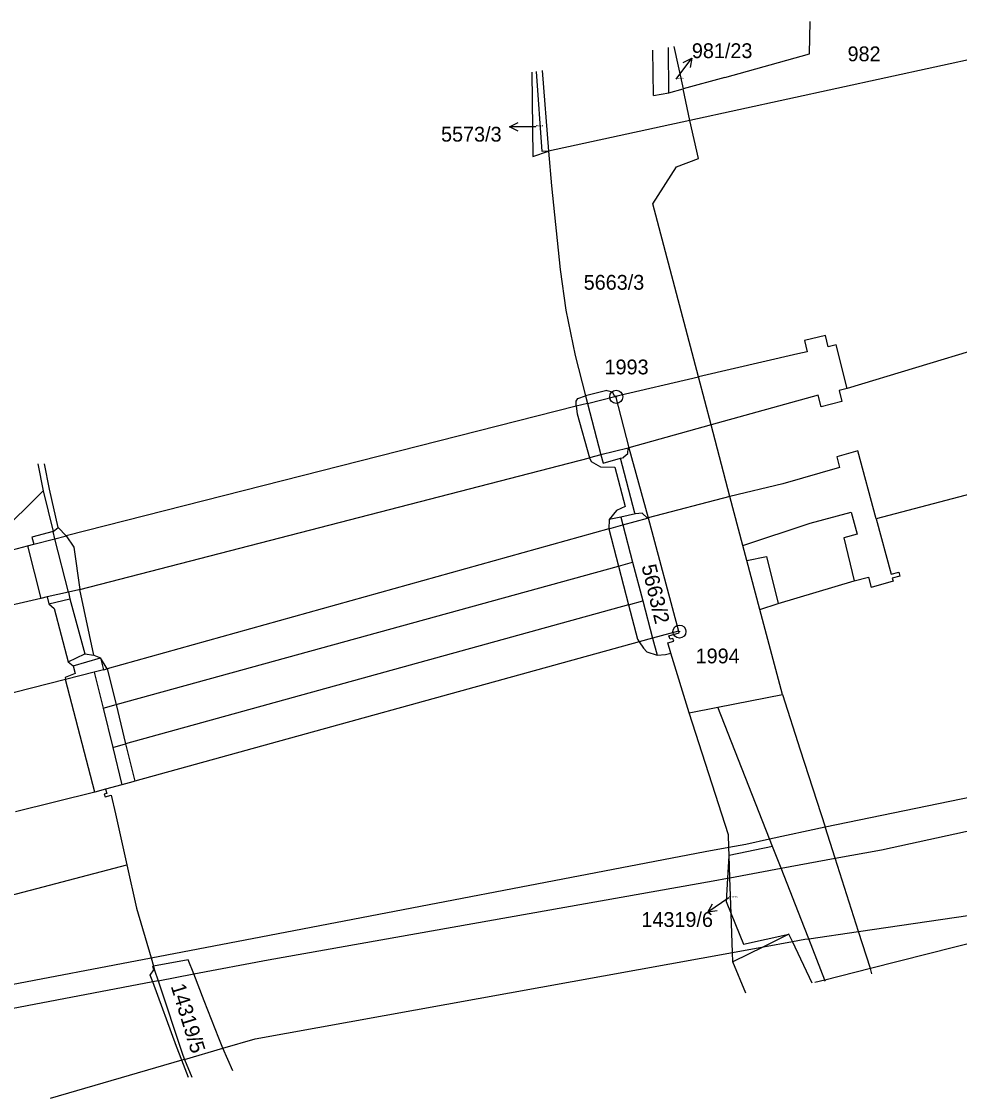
# Model space of a CAD drawing. Extents: x -825057 to -819383, y -1071633 to -1067888.
# Drawn here: x -822297.9 to -822190.2, y -1070466.7 to -1070343 of the extents above; entities that cross this region are included whole.
import ezdxf

# ---------------------------------------------------------------- set-up
doc = ezdxf.new("R2010")
doc.units = 0
for name, color, linetype in [('Vrstva 1', 7, 'Continuous'), ('Vrstva 16', 7, 'Continuous'), ('Vrstva 17', 7, 'Continuous'), ('Vrstva 18', 7, 'Continuous'), ('Vrstva 24', 7, 'Continuous'), ('Vrstva 4', 7, 'Continuous')]:
    doc.layers.add(name, color=color, linetype=linetype)

msp = doc.modelspace()

# ---------------------------------------------------------------- linework, layer by layer
at = {"layer": 'Vrstva 1'}
for p, q in [((-822207.39, -1070346.71), (-822207.31, -1070342.99)), ((-822065.38, -1070343.33), (-822203.06, -1070385.13)), ((-822223.55, -1070351.18), (-822223.57, -1070345.96)), ((-822222.96, -1070345.85), (-822221.89, -1070350.73)), ((-822182.14, -1070345.88), (-822221.11, -1070354.34)), ((-822217.12, -1070349.42), (-822207.39, -1070346.71)), ((-822239.25, -1070348.82), (-822239.15, -1070358.5)), ((-822238.07, -1070348.61), (-822237.35, -1070357.87)), ((-822217.12, -1070349.42), (-822221.89, -1070350.73)), ((-822223.55, -1070351.18), (-822221.89, -1070350.73)), ((-822221.11, -1070354.34), (-822221.89, -1070350.73)), ((-822221.11, -1070354.34), (-822237.35, -1070357.87)), ((-822220.13, -1070358.73), (-822221.11, -1070354.34)), ((-822239.15, -1070358.5), (-822237.35, -1070357.87)), ((-822237.35, -1070357.87), (-822237, -1070361.87)), ((-822222.67, -1070359.66), (-822220.13, -1070358.73)), ((-822225.38, -1070363.92), (-822222.67, -1070359.66)), ((-822237, -1070361.87), (-822236.02, -1070371.46)), ((-822060.87, -1070363.29), (-822199.72, -1070400.12)), ((-822220.14, -1070383.79), (-822225.38, -1070363.92)), ((-822236.02, -1070371.46), (-822235.38, -1070376.15)), ((-822235.38, -1070376.15), (-822234.28, -1070381.35)), ((-822205.53, -1070379.06), (-822207.95, -1070379.62)), ((-822207.95, -1070379.62), (-822207.65, -1070380.91)), ((-822205.23, -1070380.33), (-822205.53, -1070379.06)), ((-822207.65, -1070380.91), (-822208.73, -1070381.16)), ((-822204.32, -1070380.12), (-822205.23, -1070380.33)), ((-822203.06, -1070385.13), (-822204.32, -1070380.12)), ((-822234.28, -1070381.35), (-822233.12, -1070385.96)), ((-822208.73, -1070381.16), (-822220.14, -1070383.79)), ((-822218.69, -1070389.32), (-822220.14, -1070383.79)), ((-822230.65, -1070385.36), (-822233.12, -1070385.96)), ((-822233.12, -1070385.96), (-822232.89, -1070386.85)), ((-822230.63, -1070385.42), (-822230.65, -1070385.36)), ((-822230.02, -1070385.57), (-822230.63, -1070385.42)), ((-822229.74, -1070386.04), (-822230.02, -1070385.57)), ((-822229.67, -1070386.02), (-822229.74, -1070386.04)), ((-822229.67, -1070386.02), (-822228.14, -1070391.95)), ((-822232.89, -1070386.85), (-822234.17, -1070387.18)), ((-822234.17, -1070387.18), (-822234.07, -1070388.06)), ((-822234.07, -1070388.06), (-822232.64, -1070393.1)), ((-822216.52, -1070397.53), (-822218.69, -1070389.32)), ((-822228.14, -1070391.95), (-822225.92, -1070400)), ((-822232.64, -1070393.1), (-822232.44, -1070393.51)), ((-822295.99, -1070393.8), (-822295.37, -1070396.87)), ((-822232.44, -1070393.51), (-822231.37, -1070394.14)), ((-822231.37, -1070394.14), (-822229.75, -1070394.15)), ((-822229.75, -1070394.15), (-822228.54, -1070398.67)), ((-822295.37, -1070396.87), (-822300.62, -1070402.06)), ((-822295.37, -1070396.87), (-822294.23, -1070401.54)), ((-822215.04, -1070403.17), (-822216.52, -1070397.53)), ((-822229.55, -1070399.16), (-822230.37, -1070400.19)), ((-822228.54, -1070398.67), (-822229.55, -1070399.16)), ((-822230.37, -1070400.19), (-822230.43, -1070401.26)), ((-822225.92, -1070400), (-822222.41, -1070413)), ((-822199.72, -1070400.12), (-822198, -1070406.45)), ((-822294.23, -1070401.54), (-822293.68, -1070401.09)), ((-822293.68, -1070401.09), (-822292.73, -1070402.05)), ((-822292.73, -1070402.05), (-822291.88, -1070403.36)), ((-822230.43, -1070401.26), (-822229.32, -1070405.52)), ((-822291.88, -1070403.36), (-822291.16, -1070408.23)), ((-822214.58, -1070404.89), (-822215.04, -1070403.17)), ((-822229.32, -1070405.52), (-822228.15, -1070409.98)), ((-822213.1, -1070410.53), (-822214.58, -1070404.89)), ((-822202.24, -1070407.22), (-822200.61, -1070406.79)), ((-822200.61, -1070406.79), (-822200.29, -1070407.97)), ((-822198, -1070406.45), (-822197.12, -1070406.21)), ((-822196.99, -1070406.69), (-822197.87, -1070406.93)), ((-822197.87, -1070406.93), (-822197.78, -1070407.26)), ((-822197.12, -1070406.21), (-822196.99, -1070406.69)), ((-822291.3, -1070408.27), (-822292.47, -1070408.53)), ((-822291.16, -1070408.23), (-822291.3, -1070408.27)), ((-822210.97, -1070409.81), (-822202.24, -1070407.22)), ((-822197.78, -1070407.26), (-822200.29, -1070407.97)), ((-822295.67, -1070409.24), (-822304.46, -1070411.3)), ((-822294.91, -1070409.07), (-822295.67, -1070409.24)), ((-822292.47, -1070408.53), (-822294.91, -1070409.07)), ((-822292.47, -1070408.53), (-822292.33, -1070409.3)), ((-822292.33, -1070409.3), (-822290.61, -1070415.61)), ((-822228.15, -1070409.98), (-822227.14, -1070413.91)), ((-822213.1, -1070410.53), (-822210.97, -1070409.81)), ((-822210.49, -1070420.26), (-822213.1, -1070410.53)), ((-822222.41, -1070413), (-822225.4, -1070413.79)), ((-822223.54, -1070413.52), (-822222.36, -1070413.18)), ((-822222.36, -1070413.18), (-822222.41, -1070413)), ((-822226.94, -1070414.22), (-822284.87, -1070430.22)), ((-822227.14, -1070413.91), (-822226.94, -1070414.22)), ((-822225.4, -1070413.79), (-822226.94, -1070414.22)), ((-822223.65, -1070414.34), (-822222.96, -1070414.15)), ((-822223.32, -1070415.54), (-822223.65, -1070414.34)), ((-822223.4, -1070413.91), (-822223.54, -1070413.52)), ((-822223.09, -1070413.84), (-822223.4, -1070413.91)), ((-822222.96, -1070414.15), (-822223.09, -1070413.84)), ((-822290.61, -1070415.61), (-822289.56, -1070415.76)), ((-822289.56, -1070415.76), (-822288.8, -1070416.05)), ((-822221.19, -1070422.39), (-822223.32, -1070415.54)), ((-822288.8, -1070416.05), (-822288.44, -1070417.43)), ((-822289.52, -1070417.71), (-822292.81, -1070418.55)), ((-822288.44, -1070417.43), (-822289.52, -1070417.71)), ((-822288.44, -1070417.43), (-822288.03, -1070417.32)), ((-822288.03, -1070417.32), (-822287.02, -1070421.43)), ((-822292.81, -1070418.55), (-822302.04, -1070420.92)), ((-822217.92, -1070421.74), (-822210.49, -1070420.26)), ((-822210.49, -1070420.26), (-822208.44, -1070426.65)), ((-822287.02, -1070421.43), (-822285.92, -1070425.95)), ((-822221.19, -1070422.39), (-822217.92, -1070421.74)), ((-822216.69, -1070436.38), (-822221.19, -1070422.39)), ((-822285.92, -1070425.95), (-822284.87, -1070430.22)), ((-822208.44, -1070426.65), (-822205.6, -1070435.48)), ((-822285.1, -1070430.29), (-822286.36, -1070430.64)), ((-822284.87, -1070430.22), (-822285.1, -1070430.29)), ((-822205.6, -1070435.48), (-822181.45, -1070430.48)), ((-822289.45, -1070431.49), (-822298.56, -1070433.75)), ((-822288.24, -1070431.16), (-822289.45, -1070431.49)), ((-822288.08, -1070431.63), (-822288.37, -1070431.72)), ((-822288.37, -1070431.72), (-822288.27, -1070432.02)), ((-822286.36, -1070430.64), (-822288.24, -1070431.16)), ((-822288.24, -1070431.16), (-822288.08, -1070431.63)), ((-822288.27, -1070432.02), (-822287.56, -1070431.85)), ((-822287.56, -1070431.85), (-822287.07, -1070433.97)), ((-822287.07, -1070433.97), (-822285.76, -1070439.85)), ((-822216.64, -1070437.82), (-822216.69, -1070436.38)), ((-822216.61, -1070438.78), (-822216.64, -1070437.82)), ((-822216.64, -1070438.79), (-822216.79, -1070441.37)), ((-822216.61, -1070438.78), (-822216.64, -1070438.79)), ((-822216.52, -1070441.32), (-822216.61, -1070438.78)), ((-822305.9, -1070445.1), (-822285.76, -1070439.85)), ((-822285.76, -1070439.85), (-822284.66, -1070444.82)), ((-822216.79, -1070441.37), (-822216.94, -1070444.04)), ((-822216.37, -1070445.45), (-822216.52, -1070441.32)), ((-822216.94, -1070444.04), (-822216.37, -1070445.45)), ((-822284.66, -1070444.82), (-822283, -1070450.52)), ((-822216.22, -1070449.9), (-822216.37, -1070445.45)), ((-822209.74, -1070447.82), (-822212.68, -1070449.26)), ((-822209.34, -1070448.65), (-822209.74, -1070447.82)), ((-822207.07, -1070453.41), (-822209.34, -1070448.65)), ((-822216.18, -1070450.97), (-822216.22, -1070449.9)), ((-822212.68, -1070449.26), (-822216.18, -1070450.97)), ((-822283, -1070450.52), (-822282.72, -1070451.47)), ((-822278.72, -1070450.74), (-822282.72, -1070451.47)), ((-822282.72, -1070451.47), (-822282.59, -1070451.93)), ((-822278.09, -1070452.37), (-822278.72, -1070450.74)), ((-822214.71, -1070454.57), (-822216.18, -1070450.97)), ((-822282.59, -1070451.93), (-822282.19, -1070453.15)), ((-822276.91, -1070455.44), (-822278.09, -1070452.37)), ((-822282.19, -1070453.15), (-822279.36, -1070461.71)), ((-822275.23, -1070459.76), (-822276.91, -1070455.44)), ((-822274.74, -1070460.9), (-822275.23, -1070459.76)), ((-822273.62, -1070463.5), (-822274.74, -1070460.9)), ((-822279.36, -1070461.71), (-822279.16, -1070462.19)), ((-822279.16, -1070462.19), (-822278.33, -1070464.21))]:
    msp.add_line(p, q, dxfattribs=at)
at = {"layer": 'Vrstva 16'}
for p, q in [((-822222.68, -1070349.59), (-822220.886, -1070347.185)), ((-822238.82, -1070355.08), (-822241.82, -1070355.08)), ((-822238.81, -1070355.08), (-822238.82, -1070355.08)), ((-822216.66, -1070443.62), (-822219.061, -1070445.264))]:
    msp.add_line(p, q, dxfattribs=at)
for points in [[(-822221.885, -1070347.688), (-822220.886, -1070347.185), (-822221.083, -1070348.286)], [(-822240.82, -1070355.58), (-822241.82, -1070355.08), (-822240.82, -1070354.58)], [(-822217.987, -1070445.116), (-822219.061, -1070445.264), (-822218.535, -1070444.316)]]:
    msp.add_lwpolyline(points, dxfattribs=at)
at = {"layer": 'Vrstva 24'}
for centre, radius in [((-822229.58, -1070386.09), 0.75), ((-822229.58, -1070386.09), 0.0327), ((-822222.32, -1070413.05), 0.75), ((-822222.32, -1070413.05), 0.0327)]:
    msp.add_circle(centre, radius, dxfattribs=at)
at = {"layer": 'Vrstva 4'}
for p, q in [((-822225.28, -1070351.47), (-822225.38, -1070346.29)), ((-822238.1, -1070357.92), (-822238.73, -1070348.73)), ((-822225.28, -1070351.47), (-822223.55, -1070351.18)), ((-822237.35, -1070357.87), (-822238.1, -1070357.92)), ((-822229.67, -1070386.02), (-822220.14, -1070383.79)), ((-822233.97, -1070386.29), (-822233.12, -1070385.96)), ((-822232.89, -1070386.85), (-822229.74, -1070386.04)), ((-822206.4, -1070385.91), (-822218.69, -1070389.32)), ((-822206.03, -1070387.23), (-822206.4, -1070385.91)), ((-822203.06, -1070385.13), (-822203.99, -1070385.35)), ((-822203.99, -1070385.35), (-822203.67, -1070386.64)), ((-822234.17, -1070387.18), (-822292.73, -1070402.05)), ((-822234.17, -1070386.57), (-822233.97, -1070386.29)), ((-822234.17, -1070387.18), (-822234.17, -1070386.57)), ((-822232.89, -1070386.85), (-822231.33, -1070392.77)), ((-822203.67, -1070386.64), (-822206.03, -1070387.23)), ((-822218.69, -1070389.32), (-822228.14, -1070391.95)), ((-822228.2, -1070391.97), (-822231.33, -1070392.77)), ((-822228.25, -1070392.59), (-822228.2, -1070391.97)), ((-822228.14, -1070391.95), (-822228.2, -1070391.97)), ((-822291.16, -1070408.23), (-822232.64, -1070393.1)), ((-822231.33, -1070392.77), (-822232.64, -1070393.1)), ((-822231.33, -1070392.77), (-822231.08, -1070393.69)), ((-822231.08, -1070393.69), (-822229.07, -1070393.15)), ((-822229.07, -1070393.15), (-822228.69, -1070393.05)), ((-822227.43, -1070399.46), (-822229.07, -1070393.15)), ((-822228.71, -1070392.97), (-822228.25, -1070392.59)), ((-822228.69, -1070393.05), (-822228.71, -1070392.97)), ((-822201.84, -1070392.29), (-822204.24, -1070392.98)), ((-822204.24, -1070392.98), (-822203.92, -1070394.21)), ((-822199.72, -1070400.12), (-822201.84, -1070392.29)), ((-822294.64, -1070396.69), (-822295.23, -1070393.78)), ((-822203.92, -1070394.21), (-822210.43, -1070396.09)), ((-822293.68, -1070401.09), (-822294.64, -1070396.69)), ((-822210.43, -1070396.09), (-822216.52, -1070397.53)), ((-822216.52, -1070397.53), (-822225.92, -1070400)), ((-822227.35, -1070399.54), (-822229.05, -1070399.91)), ((-822227.35, -1070399.54), (-822227.43, -1070399.46)), ((-822226.58, -1070399.44), (-822227.35, -1070399.54)), ((-822226, -1070400.02), (-822226.58, -1070399.44)), ((-822207.31, -1070400.61), (-822202.58, -1070399.34)), ((-822202.58, -1070399.34), (-822201.89, -1070401.87)), ((-822230.43, -1070401.26), (-822228.81, -1070400.81)), ((-822229.05, -1070399.91), (-822230.37, -1070400.19)), ((-822229.05, -1070399.91), (-822228.81, -1070400.81)), ((-822228.81, -1070400.81), (-822226, -1070400.02)), ((-822228.81, -1070400.81), (-822227.69, -1070405.07)), ((-822225.92, -1070400), (-822226, -1070400.02)), ((-822215.04, -1070403.17), (-822207.31, -1070400.61)), ((-822294.23, -1070401.54), (-822296.67, -1070402.19)), ((-822294.03, -1070402.39), (-822294.23, -1070401.54)), ((-822294.03, -1070402.39), (-822292.87, -1070402.08)), ((-822292.87, -1070402.08), (-822292.73, -1070402.05)), ((-822230.43, -1070401.26), (-822288.03, -1070417.32)), ((-822201.89, -1070401.87), (-822203.42, -1070402.29)), ((-822306.02, -1070405.56), (-822297.18, -1070403.22)), ((-822297.18, -1070403.22), (-822296.44, -1070403.03)), ((-822297.18, -1070403.22), (-822295.67, -1070409.24)), ((-822296.67, -1070402.19), (-822296.44, -1070403.03)), ((-822296.44, -1070403.03), (-822294.03, -1070402.39)), ((-822292.47, -1070408.53), (-822294.03, -1070402.39)), ((-822203.42, -1070402.29), (-822202.24, -1070407.22)), ((-822214.58, -1070404.89), (-822212.31, -1070404.42)), ((-822212.31, -1070404.42), (-822210.97, -1070409.81)), ((-822287.02, -1070421.43), (-822229.32, -1070405.52)), ((-822229.32, -1070405.52), (-822227.69, -1070405.07)), ((-822227.69, -1070405.07), (-822226.52, -1070409.53)), ((-822289.56, -1070415.76), (-822291.16, -1070408.23)), ((-822294.91, -1070409.07), (-822294.73, -1070409.87)), ((-822294.73, -1070409.87), (-822292.33, -1070409.3)), ((-822228.15, -1070409.98), (-822226.52, -1070409.53)), ((-822226.52, -1070409.53), (-822225.4, -1070413.79)), ((-822294.73, -1070409.87), (-822294.12, -1070410.41)), ((-822294.12, -1070410.41), (-822292.53, -1070416.52)), ((-822228.15, -1070409.98), (-822285.92, -1070425.95)), ((-822226.94, -1070414.22), (-822226.46, -1070414.97)), ((-822225.4, -1070413.79), (-822224.88, -1070415.77)), ((-822292.53, -1070416.52), (-822290.61, -1070415.61)), ((-822226.46, -1070414.97), (-822226.08, -1070415.38)), ((-822226.08, -1070415.38), (-822224.88, -1070415.77)), ((-822224.88, -1070415.77), (-822223.92, -1070415.68)), ((-822223.92, -1070415.68), (-822223.32, -1070415.54)), ((-822292.53, -1070416.52), (-822291.96, -1070416.99)), ((-822291.96, -1070416.99), (-822288.8, -1070416.05)), ((-822291.96, -1070416.99), (-822291.7, -1070417.87)), ((-822288.03, -1070417.32), (-822288.8, -1070416.05)), ((-822291.7, -1070417.87), (-822292.87, -1070418.33)), ((-822289.52, -1070417.71), (-822288.51, -1070421.84)), ((-822292.87, -1070418.33), (-822292.81, -1070418.55)), ((-822289.45, -1070431.49), (-822292.81, -1070418.55)), ((-822288.51, -1070421.84), (-822287.02, -1070421.43)), ((-822288.51, -1070421.84), (-822287.4, -1070426.36)), ((-822211.96, -1070436.87), (-822217.92, -1070421.74)), ((-822287.4, -1070426.36), (-822285.92, -1070425.95)), ((-822287.4, -1070426.36), (-822286.36, -1070430.64)), ((-822199.12, -1070438.1), (-822181.48, -1070434.25)), ((-822211.96, -1070436.87), (-822205.6, -1070435.48)), ((-822204.44, -1070439.08), (-822205.6, -1070435.48)), ((-822219.37, -1070438.32), (-822216.64, -1070437.82)), ((-822216.64, -1070437.82), (-822214.69, -1070437.47)), ((-822211.62, -1070437.75), (-822216.61, -1070438.78)), ((-822214.69, -1070437.47), (-822211.96, -1070436.87)), ((-822211.62, -1070437.75), (-822211.96, -1070436.87)), ((-822210.64, -1070440.23), (-822211.62, -1070437.75)), ((-822270.38, -1070448.1), (-822219.37, -1070438.32)), ((-822210.64, -1070440.23), (-822204.44, -1070439.08)), ((-822204.44, -1070439.08), (-822199.12, -1070438.1)), ((-822201.74, -1070447.49), (-822204.44, -1070439.08)), ((-822216.52, -1070441.32), (-822210.64, -1070440.23)), ((-822207.95, -1070447.07), (-822210.64, -1070440.23)), ((-822269.55, -1070450.74), (-822218.44, -1070441.68)), ((-822218.44, -1070441.68), (-822216.79, -1070441.37)), ((-822216.79, -1070441.37), (-822216.52, -1070441.32)), ((-822201.74, -1070447.49), (-822165.38, -1070442.19)), ((-822165.23, -1070442.81), (-822200.38, -1070451.74)), ((-822216.37, -1070445.45), (-822214.97, -1070448.94)), ((-822214.97, -1070448.94), (-822209.74, -1070447.82)), ((-822207.46, -1070448.32), (-822207.95, -1070447.07)), ((-822207.46, -1070448.32), (-822201.74, -1070447.49)), ((-822200.38, -1070451.74), (-822201.74, -1070447.49)), ((-822283, -1070450.52), (-822270.38, -1070448.1)), ((-822212.68, -1070449.26), (-822209.34, -1070448.65)), ((-822209.34, -1070448.65), (-822207.91, -1070448.39)), ((-822207.91, -1070448.39), (-822207.46, -1070448.32)), ((-822205.61, -1070453.07), (-822207.46, -1070448.32)), ((-822271.05, -1070459.83), (-822216.22, -1070449.9)), ((-822216.22, -1070449.9), (-822212.68, -1070449.26)), ((-822301.4, -1070454.05), (-822283, -1070450.52)), ((-822282.8, -1070451.48), (-822282.72, -1070451.47)), ((-822282.68, -1070451.9), (-822282.8, -1070451.48)), ((-822278.09, -1070452.37), (-822269.55, -1070450.74)), ((-822283.08, -1070452.5), (-822282.68, -1070451.9)), ((-822282.8, -1070453.26), (-822283.08, -1070452.5)), ((-822282.19, -1070453.15), (-822278.09, -1070452.37)), ((-822200.38, -1070451.74), (-822205.61, -1070453.07)), ((-822200.33, -1070451.88), (-822200.38, -1070451.74)), ((-822200.21, -1070452.37), (-822200.33, -1070451.88)), ((-822282.8, -1070453.26), (-822300.94, -1070456.72)), ((-822282.19, -1070453.15), (-822282.8, -1070453.26)), ((-822280.07, -1070460.71), (-822282.8, -1070453.26)), ((-822205.61, -1070453.07), (-822206.75, -1070453.36)), ((-822205.56, -1070453.19), (-822205.61, -1070453.07)), ((-822274.74, -1070460.9), (-822271.05, -1070459.83)), ((-822279.46, -1070462.28), (-822280.07, -1070460.71)), ((-822279.16, -1070462.19), (-822274.74, -1070460.9)), ((-822279.46, -1070462.28), (-822294.58, -1070466.67)), ((-822279.16, -1070462.19), (-822279.46, -1070462.28)), ((-822278.68, -1070464.26), (-822279.46, -1070462.28))]:
    msp.add_line(p, q, dxfattribs=at)

# ---------------------------------------------------------------- texts
at = {"layer": 'Vrstva 16'}
for s, p in [('981/23', (-822220.89, -1070347.19)), ('5573/3', (-822249.696, -1070356.78)), ('14319/6', (-822226.686, -1070446.97))]:
    msp.add_text(s, height=1.7, dxfattribs=at).set_placement(p)
at = {"layer": 'Vrstva 17'}
for s, p in [('1993', (-822230.92, -1070383.51)), ('1994', (-822220.46, -1070416.7))]:
    msp.add_text(s, height=1.7, dxfattribs=at).set_placement(p)
at = {"layer": 'Vrstva 18'}
for s, height, p in [('982', 1.7, (-822203.012, -1070347.55)), ('981/23', 0.2, (-822222.68, -1070349.59)), ('5573/3', 0.2, (-822238.81, -1070355.08)), ('5663/3', 1.7, (-822233.312, -1070373.79)), ('14319/6', 0.2, (-822216.66, -1070443.62))]:
    msp.add_text(s, height=height, dxfattribs=at).set_placement(p)
for s, rotation, p in [('5663/2', 283.5, (-822226.69, -1070405.54)), ('14319/5', 287.1, (-822280.75, -1070453.77))]:
    msp.add_text(s, height=1.7, rotation=rotation, dxfattribs=at).set_placement(p)

doc.saveas('drawing.dxf')
